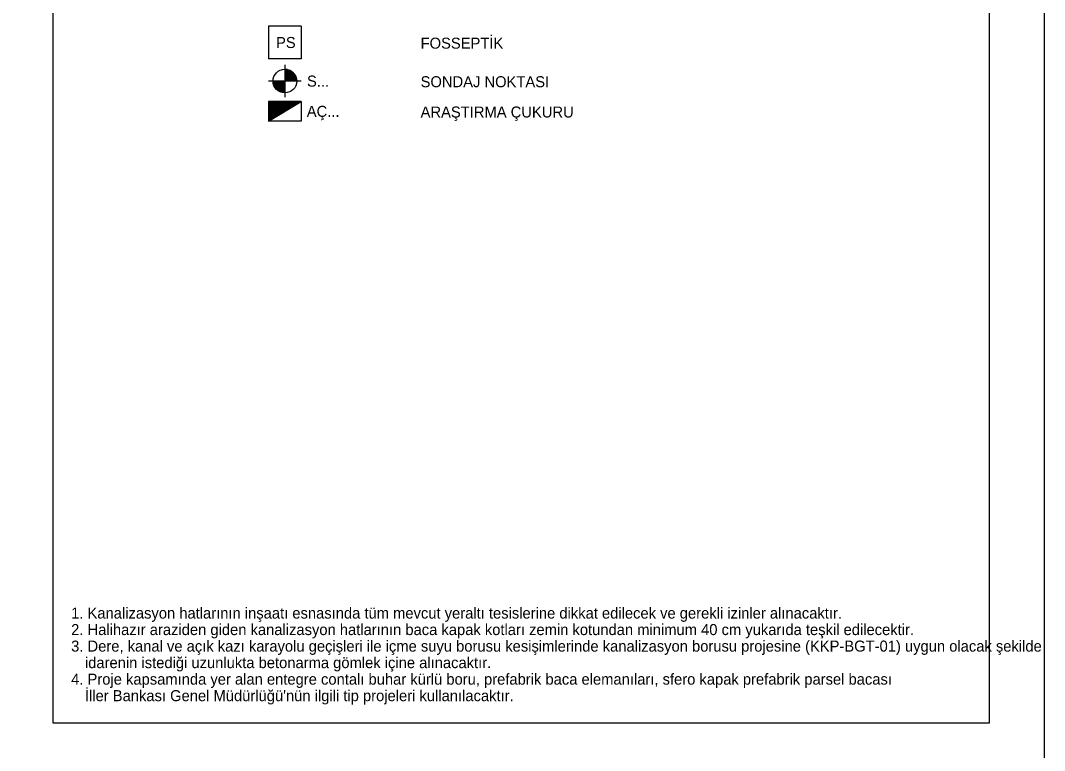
# Model space of a CAD drawing. Extents: x -10 to 821, y -10 to 550.
# Drawn here: x 635.2 to 821, y 282 to 414.6 of the extents above; entities that cross this region are included whole.
import ezdxf

# ---------------------------------------------------------------- set-up
doc = ezdxf.new("R2010")
doc.units = 0
for name, color, linetype in [('Lejand', 7, 'Continuous'), ('Level 51', 7, 'Continuous'), ('Level 52', 7, 'Continuous')]:
    doc.layers.add(name, color=color, linetype=linetype)

msp = doc.modelspace()

# ---------------------------------------------------------------- linework, layer by layer
at = {"layer": 'Lejand'}
for p, q in [((686.09, 413.5), (680.19, 413.5)), ((680.19, 413.5), (680.19, 407.6)), ((686.09, 413.5), (686.09, 407.6)), ((686.09, 407.6), (680.19, 407.6)), ((683.14, 406.5), (683.14, 400.6)), ((683.61, 405.65), (683.14, 405.65)), ((683.93, 405.55), (683.14, 405.55)), ((684.15, 405.45), (683.14, 405.45)), ((684.32, 405.35), (683.14, 405.35)), ((684.46, 405.25), (683.14, 405.25)), ((684.58, 405.15), (683.14, 405.15)), ((683.24, 405.7), (683.24, 403.55)), ((683.34, 405.69), (683.34, 403.55)), ((683.44, 405.68), (683.44, 403.55)), ((683.54, 405.66), (683.54, 403.55)), ((683.64, 405.64), (683.64, 403.55)), ((683.74, 405.62), (683.74, 403.55)), ((683.84, 405.58), (683.84, 403.55)), ((683.94, 405.55), (683.94, 403.55)), ((684.04, 405.5), (684.04, 403.55)), ((684.14, 405.45), (684.14, 403.55)), ((684.24, 405.4), (684.24, 403.55)), ((684.34, 405.33), (684.34, 403.55)), ((684.44, 405.26), (684.44, 403.55)), ((684.54, 405.18), (684.54, 403.55)), ((686.09, 403.55), (680.19, 403.55)), ((683.14, 403.45), (680.99, 403.45)), ((683.14, 403.35), (681, 403.35)), ((681.04, 403.55), (681.04, 403.09)), ((681.14, 403.55), (681.14, 402.76)), ((681.24, 403.55), (681.24, 402.54)), ((681.34, 403.55), (681.34, 402.37)), ((681.44, 403.55), (681.44, 402.23)), ((681.54, 403.55), (681.54, 402.11)), ((681.64, 403.55), (681.64, 402.01)), ((681.74, 403.55), (681.74, 401.92)), ((681.84, 403.55), (681.84, 401.84)), ((681.94, 403.55), (681.94, 401.77)), ((682.04, 403.55), (682.04, 401.7)), ((682.14, 403.55), (682.14, 401.65)), ((682.24, 403.55), (682.24, 401.6)), ((682.34, 403.55), (682.34, 401.55)), ((682.44, 403.55), (682.44, 401.52)), ((682.54, 403.55), (682.54, 401.49)), ((682.64, 403.55), (682.64, 401.46)), ((682.74, 403.55), (682.74, 401.44)), ((682.84, 403.55), (682.84, 401.42)), ((682.94, 403.55), (682.94, 401.41)), ((683.04, 403.55), (683.04, 401.4)), ((684.68, 405.05), (683.14, 405.05)), ((684.77, 404.95), (683.14, 404.95)), ((684.86, 404.85), (683.14, 404.85)), ((684.93, 404.75), (683.14, 404.75)), ((684.99, 404.65), (683.14, 404.65)), ((685.05, 404.55), (683.14, 404.55)), ((685.1, 404.45), (683.14, 404.45)), ((685.14, 404.35), (683.14, 404.35)), ((685.18, 404.25), (683.14, 404.25)), ((685.21, 404.15), (683.14, 404.15)), ((685.23, 404.05), (683.14, 404.05)), ((685.26, 403.95), (683.14, 403.95)), ((685.27, 403.85), (683.14, 403.85)), ((685.28, 403.75), (683.14, 403.75)), ((685.29, 403.65), (683.14, 403.65)), ((684.64, 405.09), (684.64, 403.55)), ((684.74, 404.99), (684.74, 403.55)), ((684.84, 404.87), (684.84, 403.55)), ((684.94, 404.73), (684.94, 403.55)), ((685.04, 404.56), (685.04, 403.55)), ((685.14, 404.34), (685.14, 403.55)), ((685.24, 404.01), (685.24, 403.55)), ((683.14, 403.25), (681.01, 403.25)), ((683.14, 403.15), (681.03, 403.15)), ((683.14, 403.05), (681.05, 403.05)), ((683.14, 402.95), (681.08, 402.95)), ((683.14, 402.85), (681.11, 402.85)), ((683.14, 402.75), (681.15, 402.75)), ((683.14, 402.65), (681.19, 402.65)), ((683.14, 402.55), (681.24, 402.55)), ((683.14, 402.45), (681.29, 402.45)), ((683.14, 402.35), (681.36, 402.35)), ((683.14, 402.25), (681.43, 402.25)), ((683.14, 402.15), (681.51, 402.15)), ((683.14, 402.05), (681.6, 402.05)), ((683.14, 401.95), (681.71, 401.95)), ((683.14, 401.85), (681.83, 401.85)), ((683.14, 401.75), (681.97, 401.75)), ((683.14, 401.65), (682.13, 401.65)), ((683.14, 401.55), (682.35, 401.55)), ((683.14, 401.45), (682.68, 401.45)), ((686.09, 399.85), (680.19, 399.85)), ((680.19, 399.85), (680.19, 396.25)), ((680.19, 396.25), (686.09, 399.85)), ((685.93, 399.75), (680.19, 399.75)), ((685.76, 399.65), (680.19, 399.65)), ((680.29, 399.85), (680.29, 396.31)), ((680.39, 399.85), (680.39, 396.37)), ((680.49, 399.85), (680.49, 396.43)), ((680.59, 399.85), (680.59, 396.49)), ((680.69, 399.85), (680.69, 396.56)), ((680.79, 399.85), (680.79, 396.62)), ((680.89, 399.85), (680.89, 396.68)), ((680.99, 399.85), (680.99, 396.74)), ((681.09, 399.85), (681.09, 396.8)), ((681.19, 399.85), (681.19, 396.86)), ((681.29, 399.85), (681.29, 396.92)), ((681.39, 399.85), (681.39, 396.98)), ((681.49, 399.85), (681.49, 397.04)), ((681.59, 399.85), (681.59, 397.1)), ((681.69, 399.85), (681.69, 397.17)), ((681.79, 399.85), (681.79, 397.23)), ((681.89, 399.85), (681.89, 397.29)), ((681.99, 399.85), (681.99, 397.35)), ((682.09, 399.85), (682.09, 397.41)), ((682.19, 399.85), (682.19, 397.47)), ((682.29, 399.85), (682.29, 397.53)), ((682.39, 399.85), (682.39, 397.59)), ((682.49, 399.85), (682.49, 397.65)), ((682.59, 399.85), (682.59, 397.71)), ((682.69, 399.85), (682.69, 397.78)), ((682.79, 399.85), (682.79, 397.84)), ((682.89, 399.85), (682.89, 397.9)), ((682.99, 399.85), (682.99, 397.96)), ((683.09, 399.85), (683.09, 398.02)), ((683.19, 399.85), (683.19, 398.08)), ((683.29, 399.85), (683.29, 398.14)), ((683.39, 399.85), (683.39, 398.2)), ((683.49, 399.85), (683.49, 398.26)), ((683.59, 399.85), (683.59, 398.32)), ((683.69, 399.85), (683.69, 398.39)), ((683.79, 399.85), (683.79, 398.45)), ((683.89, 399.85), (683.89, 398.51)), ((683.99, 399.85), (683.99, 398.57)), ((684.09, 399.85), (684.09, 398.63)), ((684.19, 399.85), (684.19, 398.69)), ((684.29, 399.85), (684.29, 398.75)), ((684.39, 399.85), (684.39, 398.81)), ((684.49, 399.85), (684.49, 398.87)), ((684.59, 399.85), (684.59, 398.94)), ((684.69, 399.85), (684.69, 399)), ((684.79, 399.85), (684.79, 399.06)), ((684.89, 399.85), (684.89, 399.12)), ((684.99, 399.85), (684.99, 399.18)), ((685.09, 399.85), (685.09, 399.24)), ((685.19, 399.85), (685.19, 399.3)), ((685.29, 399.85), (685.29, 399.36)), ((685.39, 399.85), (685.39, 399.42)), ((685.49, 399.85), (685.49, 399.48)), ((685.59, 399.85), (685.59, 399.55)), ((685.69, 399.85), (685.69, 399.61)), ((685.79, 399.85), (685.79, 399.67)), ((685.89, 399.85), (685.89, 399.73)), ((685.99, 399.85), (685.99, 399.79)), ((686.09, 399.85), (686.09, 396.25)), ((685.6, 399.55), (680.19, 399.55)), ((685.44, 399.45), (680.19, 399.45)), ((685.27, 399.35), (680.19, 399.35)), ((685.11, 399.25), (680.19, 399.25)), ((684.94, 399.15), (680.19, 399.15)), ((684.78, 399.05), (680.19, 399.05)), ((684.62, 398.95), (680.19, 398.95)), ((684.45, 398.85), (680.19, 398.85)), ((684.29, 398.75), (680.19, 398.75)), ((684.13, 398.65), (680.19, 398.65)), ((683.96, 398.55), (680.19, 398.55)), ((683.8, 398.45), (680.19, 398.45)), ((683.63, 398.35), (680.19, 398.35)), ((683.47, 398.25), (680.19, 398.25)), ((683.31, 398.15), (680.19, 398.15)), ((683.14, 398.05), (680.19, 398.05)), ((682.98, 397.95), (680.19, 397.95)), ((682.81, 397.85), (680.19, 397.85)), ((682.65, 397.75), (680.19, 397.75)), ((682.49, 397.65), (680.19, 397.65)), ((682.32, 397.55), (680.19, 397.55)), ((682.16, 397.45), (680.19, 397.45)), ((681.99, 397.35), (680.19, 397.35)), ((681.83, 397.25), (680.19, 397.25)), ((681.67, 397.15), (680.19, 397.15)), ((681.5, 397.05), (680.19, 397.05)), ((681.34, 396.95), (680.19, 396.95)), ((681.18, 396.85), (680.19, 396.85)), ((681.01, 396.75), (680.19, 396.75)), ((680.85, 396.65), (680.19, 396.65)), ((680.68, 396.55), (680.19, 396.55)), ((680.52, 396.45), (680.19, 396.45)), ((680.36, 396.35), (680.19, 396.35)), ((686.09, 396.25), (680.19, 396.25))]:
    msp.add_line(p, q, dxfattribs=at)
msp.add_circle((683.14, 403.55), 2.15, dxfattribs=at)
at = {"layer": 'Level 51'}
msp.add_lwpolyline([(-10, -10), (821, -10), (821, 550), (-10, 550)], close=True, dxfattribs=at)
at = {"layer": 'Level 52'}
msp.add_lwpolyline([(641, 287), (811, 287), (811, 540), (641, 540)], close=True, dxfattribs=at)

# ---------------------------------------------------------------- texts
at = {"layer": 'Lejand'}
for s, p in [('PS', (681.53, 409.55)), ('S...', (687.15, 402.55)), ('SONDAJ NOKTASI', (707.77, 402.43)), ('AÇ...', (687.11, 397.05)), ('ARAŞTIRMA ÇUKURU', (707.77, 396.93))]:
    msp.add_text(s, height=2, rotation=0.0008, dxfattribs=at).set_placement(p)
for s, p in [('FOSSEPTİK', (707.77, 409.43)), ('1. Kanalizasyon hatlarının inşaatı esnasında tüm mevcut yeraltı tesislerine dikkat edilecek ve gerekli izinler alınacaktır.', (644.35, 305.96)), ('2. Halihazır araziden giden kanalizasyon hatlarının baca kapak kotları zemin kotundan minimum 40 cm yukarıda teşkil edilecektir.', (644.35, 302.96)), ('3. Dere, kanal ve açık kazı karayolu geçişleri ile içme suyu borusu kesişimlerinde kanalizasyon borusu projesine (KKP-BGT-01) uygun olacak şekilde', (644.35, 299.96)), ('idarenin istediği uzunlukta betonarma gömlek içine alınacaktır.', (646.85, 296.96)), ('4. Proje kapsamında yer alan entegre contalı buhar kürlü boru, prefabrik baca elemanıları, sfero kapak prefabrik parsel bacası', (644.35, 293.96)), ("İller Bankası Genel Müdürlüğü'nün ilgili tip projeleri kullanılacaktır.", (646.85, 290.96))]:
    msp.add_text(s, height=2, dxfattribs=at).set_placement(p)

doc.saveas('drawing.dxf')
